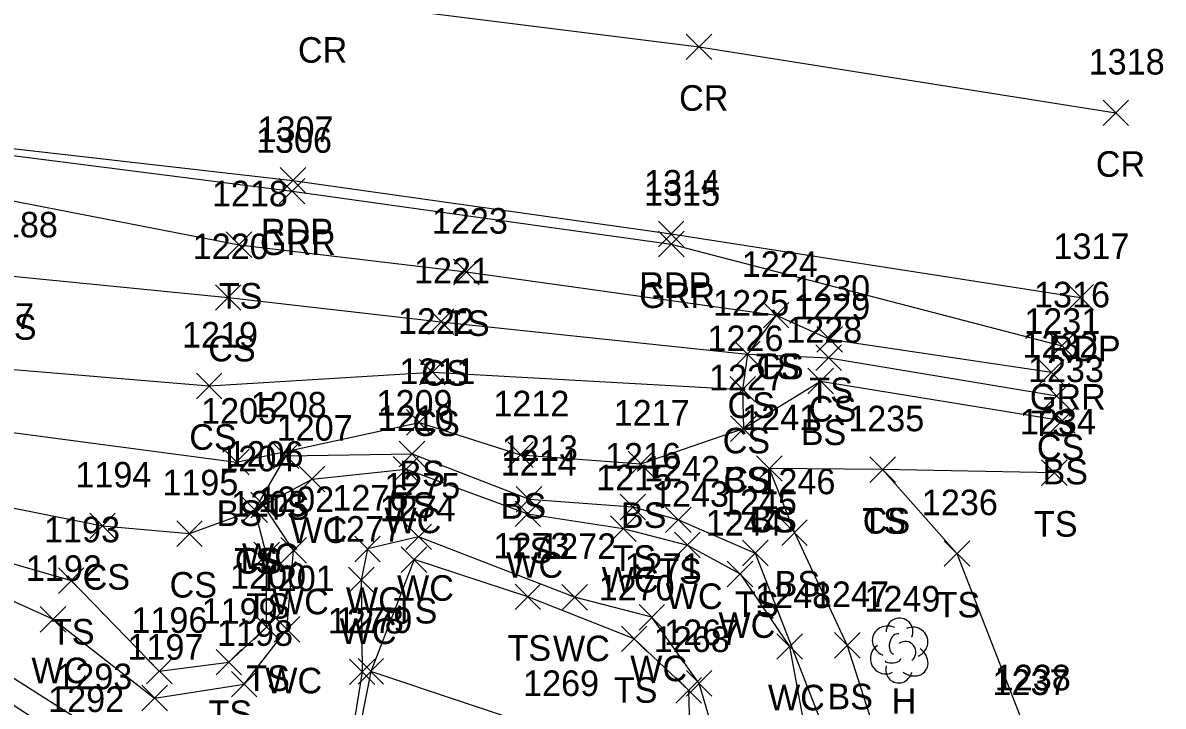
# Model space of a CAD drawing. Extents: x 1514253 to 1516033, y 782541 to 785002.
# Drawn here: x 1515367.9 to 1515457.2, y 782634.2 to 782687.6 of the extents above; entities that cross this region are included whole.
import ezdxf

# ---------------------------------------------------------------- set-up
doc = ezdxf.new("R2010")
doc.units = 0
for name, color, linetype in [('L_A', 7, 'Continuous'), ('L_I', 7, 'Continuous'), ('L_TIC', 7, 'Continuous'), ('LAWE', 7, 'Continuous'), ('LELB', 7, 'Continuous'), ('LTD', 7, 'Continuous'), ('M_I', 7, 'Continuous'), ('P_A', 7, 'Continuous'), ('P_I', 7, 'Continuous'), ('P_TIC', 7, 'Continuous'), ('PET', 7, 'Continuous'), ('PRC', 7, 'Continuous'), ('R_A', 7, 'Continuous'), ('R_I', 7, 'Continuous'), ('R_TIC', 7, 'Continuous'), ('RGR', 7, 'Continuous')]:
    doc.layers.add(name, color=color, linetype=linetype)

msp = doc.modelspace()

# ---------------------------------------------------------------- linework, layer by layer
at = {"layer": 'L_TIC'}
for points in [[(1515383.856, 782669.273), (1515385.856, 782671.273)], [(1515385.856, 782669.273), (1515383.856, 782671.273)], [(1515401.641, 782667.137), (1515403.641, 782669.137)], [(1515403.641, 782667.137), (1515401.641, 782669.137)], [(1515383.002, 782665.142), (1515385.002, 782667.142)], [(1515385.002, 782665.142), (1515383.002, 782667.142)], [(1515399.676, 782663.245), (1515401.676, 782665.245)], [(1515401.676, 782663.245), (1515399.676, 782665.245)], [(1515425.898, 782663.758), (1515427.898, 782665.758)], [(1515427.898, 782663.758), (1515425.898, 782665.758)], [(1515425.898, 782663.758), (1515427.898, 782665.758)], [(1515427.898, 782663.758), (1515425.898, 782665.758)], [(1515430.084, 782661.879), (1515432.084, 782663.879)], [(1515432.084, 782661.879), (1515430.084, 782663.879)], [(1515423.648, 782660.721), (1515425.648, 782662.721)], [(1515425.648, 782660.721), (1515423.648, 782662.721)], [(1515423.648, 782660.721), (1515425.648, 782662.721)], [(1515425.648, 782660.721), (1515423.648, 782662.721)], [(1515430.013, 782660.432), (1515432.013, 782662.432)], [(1515432.013, 782660.432), (1515430.013, 782662.432)], [(1515398.983, 782659.3), (1515400.983, 782661.3)], [(1515400.983, 782659.3), (1515398.983, 782661.3)], [(1515429.378, 782658.607), (1515431.378, 782660.607)], [(1515431.378, 782658.607), (1515429.378, 782660.607)], [(1515447.442, 782659.296), (1515449.442, 782661.296)], [(1515449.442, 782659.296), (1515447.442, 782661.296)], [(1515381.517, 782658.229), (1515383.517, 782660.229)], [(1515383.517, 782658.229), (1515381.517, 782660.229)], [(1515423.268, 782657.95), (1515425.268, 782659.95)], [(1515425.268, 782657.95), (1515423.268, 782659.95)], [(1515423.268, 782657.95), (1515425.268, 782659.95)], [(1515425.268, 782657.95), (1515423.268, 782659.95)], [(1515447.86, 782657.438), (1515449.86, 782659.438)], [(1515449.86, 782657.438), (1515447.86, 782659.438)], [(1515397.956, 782655.377), (1515399.956, 782657.377)], [(1515399.956, 782655.377), (1515397.956, 782657.377)], [(1515448.299, 782655.525), (1515450.299, 782657.525)], [(1515450.299, 782655.525), (1515448.299, 782657.525)], [(1515423.335, 782654.884), (1515425.335, 782656.884)], [(1515425.335, 782654.884), (1515423.335, 782656.884)], [(1515423.335, 782654.884), (1515425.335, 782656.884)], [(1515425.335, 782654.884), (1515423.335, 782656.884)], [(1515387.534, 782652.757), (1515389.534, 782654.757)], [(1515389.534, 782652.757), (1515387.534, 782654.757)], [(1515397.392, 782652.907), (1515399.392, 782654.907)], [(1515399.392, 782652.907), (1515397.392, 782654.907)], [(1515405.884, 782652.846), (1515407.884, 782654.846)], [(1515407.884, 782652.846), (1515405.884, 782654.846)], [(1515383.653, 782652.272), (1515385.653, 782654.272)], [(1515385.653, 782652.272), (1515383.653, 782654.272)], [(1515396.927, 782651.705), (1515398.927, 782653.705)], [(1515398.927, 782651.705), (1515396.927, 782653.705)], [(1515415.301, 782652.121), (1515417.301, 782654.121)], [(1515417.301, 782652.121), (1515415.301, 782654.121)], [(1515425.363, 782651.769), (1515427.363, 782653.769)], [(1515427.363, 782651.769), (1515425.363, 782653.769)], [(1515425.363, 782651.769), (1515427.363, 782653.769)], [(1515427.363, 782651.769), (1515425.363, 782653.769)], [(1515434.233, 782651.676), (1515436.233, 782653.676)], [(1515436.233, 782651.676), (1515434.233, 782653.676)], [(1515434.233, 782651.676), (1515436.233, 782653.676)], [(1515436.233, 782651.676), (1515434.233, 782653.676)], [(1515447.667, 782651.433), (1515449.667, 782653.433)], [(1515449.667, 782651.433), (1515447.667, 782653.433)], [(1515389.568, 782650.945), (1515391.568, 782652.945)], [(1515391.568, 782650.945), (1515389.568, 782652.945)], [(1515385.777, 782648.906), (1515387.777, 782650.906)], [(1515387.777, 782648.906), (1515385.777, 782650.906)], [(1515406.552, 782649.359), (1515408.552, 782651.359)], [(1515408.552, 782649.359), (1515406.552, 782651.359)], [(1515414.675, 782648.762), (1515416.675, 782650.762)], [(1515416.675, 782648.762), (1515414.675, 782650.762)], [(1515385.077, 782648.544), (1515387.077, 782650.544)], [(1515387.077, 782648.544), (1515385.077, 782650.544)], [(1515385.077, 782648.544), (1515387.077, 782650.544)], [(1515387.077, 782648.544), (1515385.077, 782650.544)], [(1515406.459, 782648.219), (1515408.459, 782650.219)], [(1515408.459, 782648.219), (1515406.459, 782650.219)], [(1515373.165, 782647.283), (1515375.165, 782649.283)], [(1515375.165, 782647.283), (1515373.165, 782649.283)], [(1515413.933, 782647.068), (1515415.933, 782649.068)], [(1515415.933, 782647.068), (1515413.933, 782649.068)], [(1515418.247, 782647.751), (1515420.247, 782649.751)], [(1515420.247, 782647.751), (1515418.247, 782649.751)], [(1515379.971, 782646.67), (1515381.971, 782648.67)], [(1515381.971, 782646.67), (1515379.971, 782648.67)], [(1515397.91, 782646.419), (1515399.91, 782648.419)], [(1515399.91, 782646.419), (1515397.91, 782648.419)], [(1515427.334, 782646.754), (1515429.334, 782648.754)], [(1515429.334, 782646.754), (1515427.334, 782648.754)], [(1515388.121, 782645.36), (1515390.121, 782647.36)], [(1515390.121, 782645.36), (1515388.121, 782647.36)], [(1515393.909, 782645.476), (1515395.909, 782647.476)], [(1515395.909, 782645.476), (1515393.909, 782647.476)], [(1515418.945, 782645.777), (1515420.945, 782647.777)], [(1515420.945, 782645.777), (1515418.945, 782647.777)], [(1515386.011, 782645.011), (1515388.011, 782647.011)], [(1515388.011, 782645.011), (1515386.011, 782647.011)], [(1515397.549, 782644.643), (1515399.549, 782646.643)], [(1515399.549, 782644.643), (1515397.549, 782646.643)], [(1515424.267, 782645.15), (1515426.267, 782647.15)], [(1515426.267, 782645.15), (1515424.267, 782647.15)], [(1515440.048, 782645.115), (1515442.048, 782647.115)], [(1515442.048, 782645.115), (1515440.048, 782647.115)], [(1515423.071, 782643.52), (1515425.071, 782645.52)], [(1515425.071, 782643.52), (1515423.071, 782645.52)], [(1515370.713, 782642.995), (1515372.713, 782644.995)], [(1515372.713, 782642.995), (1515370.713, 782644.995)], [(1515393.422, 782643.041), (1515395.422, 782645.041)], [(1515395.422, 782643.041), (1515393.422, 782645.041)], [(1515406.458, 782641.731), (1515408.458, 782643.731)], [(1515408.458, 782641.731), (1515406.458, 782643.731)], [(1515410.117, 782641.694), (1515412.117, 782643.694)], [(1515412.117, 782641.694), (1515410.117, 782643.694)], [(1515369.291, 782639.974), (1515371.291, 782641.974)], [(1515371.291, 782639.974), (1515369.291, 782641.974)], [(1515416.164, 782640.13), (1515418.164, 782642.13)], [(1515418.164, 782640.13), (1515416.164, 782642.13)], [(1515386.007, 782639.366), (1515388.007, 782641.366)], [(1515388.007, 782639.366), (1515386.007, 782641.366)], [(1515387.599, 782639.179), (1515389.599, 782641.179)], [(1515389.599, 782639.179), (1515387.599, 782641.179)], [(1515414.778, 782638.443), (1515416.778, 782640.443)], [(1515416.778, 782638.443), (1515414.778, 782640.443)], [(1515426.947, 782637.847), (1515428.947, 782639.847)], [(1515428.947, 782637.847), (1515426.947, 782639.847)], [(1515431.468, 782637.929), (1515433.468, 782639.929)], [(1515433.468, 782637.929), (1515431.468, 782639.929)], [(1515383.051, 782636.622), (1515385.051, 782638.622)], [(1515385.051, 782636.622), (1515383.051, 782638.622)], [(1515377.608, 782635.912), (1515379.608, 782637.912)], [(1515379.608, 782635.912), (1515377.608, 782637.912)], [(1515393.489, 782635.861), (1515395.489, 782637.861)], [(1515395.489, 782635.861), (1515393.489, 782637.861)], [(1515394.171, 782635.9), (1515396.171, 782637.9)], [(1515396.171, 782635.9), (1515394.171, 782637.9)], [(1515394.171, 782635.9), (1515396.171, 782637.9)], [(1515396.171, 782635.9), (1515394.171, 782637.9)], [(1515384.256, 782634.895), (1515386.256, 782636.895)], [(1515386.256, 782634.895), (1515384.256, 782636.895)], [(1515419.872, 782634.955), (1515421.872, 782636.955)], [(1515421.872, 782634.955), (1515419.872, 782636.955)], [(1515377.24, 782633.81), (1515379.24, 782635.81)], [(1515379.24, 782633.81), (1515377.24, 782635.81)], [(1515419.055, 782634.411), (1515421.055, 782636.411)], [(1515421.055, 782634.411), (1515419.055, 782636.411)]]:
    msp.add_lwpolyline(points, dxfattribs=at)
at = {"layer": 'LAWE'}
for points in [[(1515305.221, 782658.389), (1515309.247, 782657.829), (1515309.37, 782656.024), (1515310.661, 782652.237), (1515328.158, 782651.8), (1515339.372, 782649.611), (1515359.133, 782646.008), (1515370.291, 782640.974), (1515378.24, 782634.81), (1515385.256, 782635.895), (1515388.599, 782640.179), (1515389.121, 782646.36), (1515386.777, 782649.906), (1515390.568, 782651.945), (1515397.927, 782652.705), (1515407.459, 782649.219), (1515414.933, 782648.068), (1515419.945, 782646.777), (1515424.071, 782644.52), (1515427.947, 782638.847), (1515430.432, 782625.437), (1515426.178, 782619.034), (1515431.378, 782612.516)], [(1515425.881, 782608.624), (1515417.686, 782620.679), (1515422.974, 782628.809), (1515420.872, 782635.955), (1515417.164, 782641.13), (1515411.117, 782642.694), (1515398.91, 782647.419), (1515394.909, 782646.476), (1515394.422, 782644.041), (1515394.489, 782636.861), (1515393.182, 782628.813), (1515387.524, 782628.807), (1515379.253, 782626.313), (1515373.238, 782632.504), (1515362.112, 782639.578)]]:
    msp.add_lwpolyline(points, dxfattribs=at)
at = {"layer": 'LELB'}
for points in [[(1515198.723, 782678.684), (1515237.654, 782681.037), (1515272.581, 782680.406), (1515290.322, 782679.158), (1515303.85, 782678.499), (1515308.9, 782677.477), (1515327.05, 782677.392), (1515347.388, 782677.23), (1515355.314, 782675.991), (1515384.856, 782670.273), (1515402.641, 782668.137), (1515426.898, 782664.758), (1515431.084, 782662.879), (1515448.442, 782660.296)], [(1515199.146, 782675.609), (1515237.424, 782674.791), (1515272.569, 782675.732), (1515289.461, 782673.873), (1515300.027, 782673.178), (1515309.403, 782672.939), (1515327.016, 782671.989), (1515352.175, 782674.367), (1515355.484, 782668.368), (1515355.529, 782661.896), (1515362.199, 782656.243), (1515384.653, 782653.272), (1515398.956, 782656.377), (1515406.884, 782653.846), (1515416.301, 782653.121), (1515424.335, 782655.884), (1515430.378, 782659.607), (1515449.299, 782656.525)], [(1515199.887, 782668.087), (1515237.312, 782668.583), (1515273.401, 782672.059), (1515287.729, 782668.029), (1515299.264, 782668.757), (1515308.354, 782666.42), (1515328.224, 782666.061), (1515330.533, 782661.03), (1515333.755, 782659.052), (1515343.884, 782659.192), (1515351.413, 782658.187), (1515355.484, 782668.368), (1515366.848, 782667.84), (1515384.002, 782666.142), (1515400.676, 782664.245), (1515424.648, 782661.721), (1515431.013, 782661.432), (1515448.86, 782658.438)], [(1515426.898, 782664.758), (1515424.648, 782661.721), (1515424.268, 782658.95), (1515424.335, 782655.884)], [(1515284.508, 782654.562), (1515294.334, 782657.273), (1515301.485, 782657.951), (1515303.943, 782660.043), (1515308.932, 782660.064), (1515315.851, 782658.437), (1515327.358, 782657.995), (1515341.712, 782655.566), (1515348.371, 782655.012), (1515351.413, 782658.187), (1515355.529, 782661.896), (1515364.984, 782660.684), (1515382.517, 782659.229), (1515399.983, 782660.3), (1515424.268, 782658.95)], [(1515309.247, 782657.829), (1515310.163, 782657.372), (1515313.696, 782656.121), (1515327.927, 782656.035), (1515341.024, 782653.35), (1515349.767, 782652.941), (1515361.602, 782650.791), (1515374.165, 782648.283), (1515380.971, 782647.67), (1515386.077, 782649.544)], [(1515310.163, 782657.372), (1515310.383, 782655.934), (1515311.738, 782653.239), (1515327.12, 782652.556), (1515340.38, 782650.599), (1515359.526, 782647.53), (1515371.713, 782643.995), (1515378.608, 782636.912), (1515384.051, 782637.622), (1515387.007, 782640.366), (1515387.011, 782646.011), (1515386.077, 782649.544), (1515388.534, 782653.757), (1515398.392, 782653.907), (1515407.552, 782650.359), (1515415.675, 782649.762), (1515419.247, 782648.751), (1515425.267, 782646.15), (1515433.214, 782625.745), (1515427.667, 782618.999), (1515432.728, 782613.436)], [(1515435.233, 782652.676), (1515426.363, 782652.769)], [(1515426.363, 782652.769), (1515428.334, 782647.754), (1515432.468, 782638.929), (1515436.521, 782626.225), (1515437.935, 782615.284)], [(1515448.667, 782652.433), (1515435.233, 782652.676), (1515441.048, 782646.115), (1515446.525, 782632.051), (1515445.859, 782626.361)], [(1515424.462, 782608.5), (1515416.13, 782621.2), (1515420.279, 782628.005), (1515420.055, 782635.411), (1515415.778, 782639.443), (1515407.458, 782642.731), (1515398.549, 782645.643), (1515395.171, 782636.9), (1515393.589, 782628.83), (1515388.008, 782625.21), (1515377.827, 782623.514), (1515372.602, 782630.72), (1515360.567, 782638.564)], [(1515420.279, 782628.005), (1515409.835, 782631.974), (1515395.171, 782636.9)]]:
    msp.add_lwpolyline(points, dxfattribs=at)
at = {"layer": 'LTD'}
msp.add_line((1515436.508, 782638.581), (1515436.508, 782638.581), dxfattribs=at)
msp.add_line((1515436.508, 782638.581), (1515436.508, 782638.581), dxfattribs=at)
msp.add_arc((1515436.555, 782640.015), 1.047, 335.52715, 180.95627, dxfattribs=at)
for centre, major_axis, ratio, start_param, end_param in [((1515435.716, 782639.247), (1.21, -0.512), 0.895232, 1.570796, 4.712389), ((1515437.549, 782639.164), (-1.141, -0.483), 0.949671, 1.570796, 4.712389), ((1515436.299, 782639.039), (-0.208, -0.792), 0.645439, 3.141593, 6.283185), ((1515437.008, 782638.414), (-0.5, 0.667), 0.989748, 3.141593, 6.283185), ((1515435.425, 782637.872), (0.584, -1.042), 0.959034, 3.141593, 6.283185), ((1515437.508, 782637.748), (-1.09, 0.792), 0.841452, 1.570796, 4.712389), ((1515436.05, 782637.831), (-0.625, -0.083), 0.423636, 0, 3.141593), ((1515436.508, 782637.081), (0.265, 1.061), 0.942809, 1.570796, 4.712389)]:
    msp.add_ellipse(centre, major_axis=major_axis, ratio=ratio, start_param=start_param, end_param=end_param, dxfattribs=at)
at = {"layer": 'P_TIC'}
for points in [[(1515419.865, 782684.748), (1515421.865, 782686.748)], [(1515421.865, 782684.748), (1515419.865, 782686.748)], [(1515452.487, 782679.583), (1515454.487, 782681.583)], [(1515454.487, 782679.583), (1515452.487, 782681.583)], [(1515388.071, 782674.303), (1515390.071, 782676.303)], [(1515390.071, 782674.303), (1515388.071, 782676.303)], [(1515417.681, 782670.113), (1515419.681, 782672.113)], [(1515419.681, 782670.113), (1515417.681, 782672.113)], [(1515449.732, 782665.149), (1515451.732, 782667.149)], [(1515451.732, 782665.149), (1515449.732, 782667.149)]]:
    msp.add_lwpolyline(points, dxfattribs=at)
at = {"layer": 'PET'}
msp.add_lwpolyline([(1515199.633, 782684.061), (1515237.525, 782684.632), (1515272.463, 782684.04), (1515305.734, 782682.962), (1515349.744, 782679.786), (1515389.071, 782675.303), (1515418.681, 782671.113), (1515450.732, 782666.149)], dxfattribs=at)
at = {"layer": 'PRC'}
msp.add_lwpolyline([(1515198.294, 782698.445), (1515237.18, 782698.993), (1515272.827, 782698.875), (1515307.336, 782697.263), (1515350.128, 782694.483), (1515391.027, 782689.505), (1515420.865, 782685.748), (1515453.487, 782680.583)], dxfattribs=at)
at = {"layer": 'R_TIC'}
for points in [[(1515388.004, 782673.461), (1515390.004, 782675.461)], [(1515390.004, 782673.461), (1515388.004, 782675.461)], [(1515417.688, 782669.319), (1515419.688, 782671.319)], [(1515419.688, 782669.319), (1515417.688, 782671.319)], [(1515448.265, 782661.37), (1515450.265, 782663.37)], [(1515450.265, 782661.37), (1515448.265, 782663.37)]]:
    msp.add_lwpolyline(points, dxfattribs=at)
at = {"layer": 'RGR'}
msp.add_lwpolyline([(1515199.059, 782680.993), (1515237.496, 782683.643), (1515272.426, 782683.075), (1515305.957, 782681.521), (1515350.167, 782679.409), (1515389.004, 782674.461), (1515418.688, 782670.319), (1515449.265, 782662.37)], dxfattribs=at)

# ---------------------------------------------------------------- texts
at = {"layer": 'L_A'}
for s, p in [('TS', (1515383.265, 782665.273)), ('TS', (1515401.051, 782663.137)), ('CS', (1515365.289, 782662.84)), ('CS', (1515382.443, 782661.142)), ('TS', (1515425.307, 782659.758)), ('CS', (1515425.338, 782659.758)), ('CS', (1515399.117, 782659.245)), ('TS', (1515429.493, 782657.879)), ('CS', (1515423.089, 782656.721)), ('CS', (1515423.089, 782656.721)), ('CS', (1515429.454, 782656.432)), ('CS', (1515398.424, 782655.3)), ('TS', (1515446.851, 782655.296)), ('CS', (1515380.958, 782654.229)), ('BS', (1515428.819, 782654.607)), ('CS', (1515422.709, 782653.95)), ('CS', (1515422.709, 782653.95)), ('CS', (1515447.301, 782653.438)), ('BS', (1515447.74, 782651.525)), ('BS', (1515397.397, 782651.377)), ('CS', (1515422.776, 782650.884)), ('BS', (1515422.776, 782650.884)), ('TS', (1515386.944, 782648.757)), ('TS', (1515396.802, 782648.907)), ('BS', (1515405.324, 782648.846)), ('BS', (1515383.094, 782648.272)), ('BS', (1515414.742, 782648.121)), ('WC', (1515388.875, 782646.945)), ('WC', (1515396.234, 782647.705)), ('CS', (1515424.804, 782647.769)), ('BS', (1515424.804, 782647.769)), ('TS', (1515433.642, 782647.676)), ('CS', (1515433.674, 782647.676)), ('TS', (1515447.076, 782647.433)), ('TS', (1515405.961, 782645.359)), ('TS', (1515384.487, 782644.544)), ('CS', (1515384.518, 782644.544)), ('WC', (1515385.084, 782644.906)), ('TS', (1515414.084, 782644.762)), ('WC', (1515405.766, 782644.219)), ('TS', (1515417.656, 782643.751)), ('CS', (1515372.606, 782643.283)), ('CS', (1515379.412, 782642.67)), ('WC', (1515413.24, 782643.068)), ('BS', (1515426.775, 782642.754)), ('WC', (1515397.217, 782642.419)), ('WC', (1515418.252, 782641.777)), ('TS', (1515385.42, 782641.011)), ('WC', (1515387.428, 782641.36)), ('WC', (1515393.216, 782641.476)), ('TS', (1515423.676, 782641.15)), ('TS', (1515439.458, 782641.115)), ('TS', (1515396.958, 782640.643)), ('TS', (1515370.123, 782638.995)), ('WC', (1515392.729, 782639.041)), ('WC', (1515422.378, 782639.52)), ('TS', (1515405.867, 782637.731)), ('WC', (1515409.424, 782637.694)), ('WC', (1515368.598, 782635.974)), ('TS', (1515385.416, 782635.366)), ('WC', (1515415.472, 782636.13)), ('WC', (1515386.906, 782635.179)), ('TS', (1515414.187, 782634.443)), ('WC', (1515426.254, 782633.847)), ('BS', (1515430.909, 782633.929)), ('H', (1515435.941, 782633.581)), ('TS', (1515382.46, 782632.622))]:
    msp.add_text(s, height=2, dxfattribs=at).set_placement(p)
at = {"layer": 'L_I'}
for s, p in [('1218', (1515382.73, 782673.273)), ('1223', (1515399.948, 782671.137)), ('1188', (1515364.722, 782670.84)), ('1220', (1515381.222, 782669.142)), ('1224', (1515424.205, 782667.758)), ('1224', (1515424.205, 782667.758)), ('1221', (1515398.55, 782667.245)), ('1230', (1515428.305, 782665.879)), ('1225', (1515421.955, 782664.721)), ('1225', (1515421.955, 782664.721)), ('1229', (1515428.312, 782664.432)), ('1187', (1515362.858, 782663.684)), ('1222', (1515397.29, 782663.3)), ('1231', (1515446.316, 782663.296)), ('1219', (1515380.383, 782662.229)), ('1228', (1515427.685, 782662.607)), ('1226', (1515421.52, 782661.95)), ('1226', (1515421.52, 782661.95)), ('1232', (1515446.167, 782661.438)), ('1233', (1515446.606, 782659.525)), ('1211', (1515397.397, 782659.377)), ('1227', (1515421.642, 782658.884)), ('1227', (1515421.642, 782658.884)), ('1208', (1515385.763, 782656.757)), ('1209', (1515395.613, 782656.907)), ('1212', (1515404.758, 782656.846)), ('1205', (1515381.881, 782656.272)), ('1217', (1515414.175, 782656.121)), ('1210', (1515395.715, 782655.705)), ('1241', (1515424.237, 782655.769)), ('1241', (1515424.237, 782655.769)), ('1235', (1515432.54, 782655.676)), ('1235', (1515432.54, 782655.676)), ('1234', (1515445.974, 782655.433)), ('1207', (1515387.796, 782654.945)), ('1213', (1515405.426, 782653.359)), ('1204', (1515383.306, 782652.544)), ('1204', (1515383.306, 782652.544)), ('1206', (1515383.95, 782652.906)), ('1216', (1515413.494, 782652.762)), ('1214', (1515405.333, 782652.219)), ('1242', (1515416.554, 782651.751)), ('1194', (1515372.039, 782651.283)), ('1195', (1515378.845, 782650.67)), ('1215', (1515412.807, 782651.068)), ('1246', (1515425.586, 782650.754)), ('1275', (1515396.217, 782650.419)), ('1243', (1515417.252, 782649.777)), ('1203', (1515384.239, 782649.011)), ('1202', (1515386.349, 782649.36)), ('1276', (1515392.16, 782649.476)), ('1245', (1515422.574, 782649.15)), ('1236', (1515438.3, 782649.115)), ('1274', (1515395.856, 782648.643)), ('1193', (1515369.587, 782646.995)), ('1277', (1515391.729, 782647.041)), ('1244', (1515421.378, 782647.52)), ('1273', (1515404.765, 782645.731)), ('1272', (1515408.424, 782645.694)), ('1192', (1515368.165, 782643.974)), ('1200', (1515384.148, 782643.366)), ('1271', (1515415.038, 782644.13)), ('1201', (1515386.394, 782643.179)), ('1270', (1515412.998, 782642.443)), ('1248', (1515425.254, 782641.847)), ('1247', (1515429.775, 782641.929)), ('1249', (1515433.807, 782641.581)), ('1196', (1515376.427, 782639.912)), ('1199', (1515381.917, 782640.622)), ('1278', (1515391.796, 782639.861)), ('1279', (1515392.471, 782639.9)), ('1279', (1515392.471, 782639.9)), ('1198', (1515383.13, 782638.895)), ('1267', (1515418.131, 782638.955)), ('1268', (1515417.315, 782638.411)), ('1197', (1515376.114, 782637.81)), ('1293', (1515370.545, 782635.504)), ('1269', (1515407.087, 782634.974)), ('1237', (1515443.832, 782635.051)), ('1292', (1515369.91, 782633.72))]:
    msp.add_text(s, height=2, dxfattribs=at).set_placement(p)
at = {"layer": 'M_I'}
msp.add_text('1238', height=2, dxfattribs=at).set_placement((1515444.011, 782635.416))
at = {"layer": 'P_A'}
for s, p in [('CR', (1515389.461, 782684.505)), ('CR', (1515419.298, 782680.748)), ('CR', (1515451.92, 782675.583)), ('RDP', (1515386.559, 782670.303)), ('RDP', (1515416.17, 782666.113)), ('RDP', (1515448.221, 782661.149))]:
    msp.add_text(s, height=2, dxfattribs=at).set_placement(p)
at = {"layer": 'P_I'}
for s, p in [('1318', (1515451.361, 782683.583)), ('1307', (1515386.299, 782678.303)), ('1314', (1515416.555, 782674.113)), ('1317', (1515448.606, 782669.149))]:
    msp.add_text(s, height=2, dxfattribs=at).set_placement(p)
at = {"layer": 'R_A'}
for p in [(1515386.492, 782669.461), (1515416.176, 782665.319), (1515446.754, 782657.37)]:
    msp.add_text('GRR', height=2, dxfattribs=at).set_placement(p)
at = {"layer": 'R_I'}
for s, p in [('1306', (1515386.177, 782677.461)), ('1315', (1515416.562, 782673.319)), ('1316', (1515447.084, 782665.37))]:
    msp.add_text(s, height=2, dxfattribs=at).set_placement(p)

doc.saveas('drawing.dxf')
